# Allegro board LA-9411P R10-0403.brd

Outline 370.15 x 241.31 mm; copper layers: TOP, GND1, IN1, GND2, IN2, IN3, VCC, IN4, GND3, BOTTOM. Coordinates in mm from the lower left corner of the outline.

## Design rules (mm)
constraint set DEFAULT: min track width 0.102
net group AUDIO_L: nets INT_SPK_L+ INT_SPK_L-
net group AUDIO_R: nets INT_SPK_R+ INT_SPK_R-
net group CLK_BUF_BCLK: nets CLK_BUF_BCLK CLK_BUF_BCLK#
net group CLK_BUF_CKSSCD: nets CLK_BUF_CKSSCD CLK_BUF_CKSSCD#
net group CLK_BUF_DMI: nets CLK_BUF_DMI CLK_BUF_DMI#
net group CLK_BUF_DOT96: nets CLK_BUF_DOT96 CLK_BUF_DOT96#
net group CLK_CPU_DMI: nets CLK_CPU_DMI CLK_CPU_DMI#
net group CLK_CPU_DPLL: nets CLK_CPU_DPLL CLK_CPU_DPLL#
net group CLK_CPU_ITP: nets CLK_CPU_ITP CLK_CPU_ITP#
net group CLK_CPU_SSC_DPLL: nets CLK_CPU_SSC_DPLL CLK_CPU_SSC_DPLL#
net group CLK_PCIE_EMB: nets CLK_PCIE_EMB CLK_PCIE_EMB#
net group CLK_PCIE_EXP: nets CLK_PCIE_EXP CLK_PCIE_EXP#
net group CLK_PCIE_LAN: nets CLK_PCIE_LAN CLK_PCIE_LAN#
net group CLK_PCIE_MINI2: nets CLK_PCIE_MINI2 CLK_PCIE_MINI2#
net group CLK_PCIE_MINI3: nets CLK_PCIE_MINI3 CLK_PCIE_MINI3#
net group CLK_PCIE_MMI: nets CLK_PCIE_MMI CLK_PCIE_MMI#
net group CLK_PCIE_VG: nets CLK_PCIE_VGA CLK_PCIE_VGA#
net group CLK_XDP: nets CLK_XDP CLK_XDP#
net group CLKA0: nets CLKA0 CLKA0#
net group CLKA1: nets CLKA1 CLKA1#
net group CLKB0: nets CLKB0 CLKB0#
net group CLKB1: nets CLKB1 CLKB1#
net group CVT_LVDS_A0: nets CVT_LVDS_A0+ CVT_LVDS_A0-
net group CVT_LVDS_A1: nets CVT_LVDS_A1+ CVT_LVDS_A1-
net group CVT_LVDS_A2: nets CVT_LVDS_A2+ CVT_LVDS_A2-
net group CVT_LVDS_ACLK: nets CVT_LVDS_ACLK+ CVT_LVDS_ACLK-
net group CVT_LVDS_B0: nets CVT_LVDS_B0+ CVT_LVDS_B0-
net group CVT_LVDS_B1: nets CVT_LVDS_B1+ CVT_LVDS_B1-
net group CVT_LVDS_B2: nets CVT_LVDS_B2+ CVT_LVDS_B2-
net group CVT_LVDS_BCLK: nets CVT_LVDS_BCLK+ CVT_LVDS_BCLK-
net group DDR_A_3: nets DDR_A_DQS3 DDR_A_DQS#3
net group DDR_A_5: nets DDR_A_DQS5 DDR_A_DQS#5
net group DDR_A_6: nets DDR_A_DQS6 DDR_A_DQS#6
net group DDR_A_7: nets DDR_A_DQS7 DDR_A_DQS#7
net group DDR_B_3: nets DDR_B_DQS3 DDR_B_DQS#3
net group DIFFPAIR0: nets BAY_SMBCLK BAY_SMBDAT
net group DIFFPAIR1: nets BC_CLK_ECE1117 BC_DAT_ECE1117
net group DIFFPAIR2: nets BC_CLK_ECE5048 BC_DAT_ECE5048
net group DIFFPAIR3: nets CARD_SMBCLK CARD_SMBDAT
net group DIFFPAIR4: nets CHARGER_SMBCLK CHARGER_SMBDAT
net group DIFFPAIR5: nets DDR_XDP_SMBCLK_R1 DDR_XDP_SMBDAT_R1
net group DIFFPAIR6: nets DDR_XDP_WAN_SMBCLK DDR_XDP_WAN_SMBDAT
net group DIFFPAIR7: nets DDR_XDP_WAN_SMBCLK_R2 DDR_XDP_WAN_SMBDAT_R2
net group DIFFPAIR8: nets DOCK_SMB_CLK DOCK_SMB_DAT
net group DIFFPAIR9: nets GPU_SMBCLK GPU_SMBDAT
net group DIFFPAIR11: nets HDMI_SCL_SINK HDMI_SDA_SINK
net group DIFFPAIR13: nets LCD_SMBCLK LCD_SMBDAT
net group DIFFPAIR14: nets PBAT_SMBCLK PBAT_SMBDAT
net group DIFFPAIR16: nets USH_SMBCLK USH_SMBDAT
net group DIFFPAIR18: nets Z4304 Z4305
net group DIFFPAIR27: nets INT_SPKL_L+ INT_SPKL_L-
net group DIFFPAIR30: nets DPD_DOCK_AUX DPD_DOCK_AUX#
net group DIFFPAIR31: nets DPC_DOCK_AUX DPC_DOCK_AUX#
net group DIFFPAIR32: nets Z5304 Z5305
net group DMI_CRX_PTX_0: nets DMI_CRX_PTX_N0 DMI_CRX_PTX_P0
net group DMI_CRX_PTX_1: nets DMI_CRX_PTX_N1 DMI_CRX_PTX_P1
net group DMI_CRX_PTX_2: nets DMI_CRX_PTX_N2 DMI_CRX_PTX_P2
net group DMI_CRX_PTX_3: nets DMI_CRX_PTX_N3 DMI_CRX_PTX_P3
net group DMI_CTX_PRX_0: nets DMI_CTX_PRX_N0 DMI_CTX_PRX_P0
net group DMI_CTX_PRX_1: nets DMI_CTX_PRX_N1 DMI_CTX_PRX_P1
net group DMI_CTX_PRX_2: nets DMI_CTX_PRX_N2 DMI_CTX_PRX_P2
net group DMI_CTX_PRX_3: nets DMI_CTX_PRX_N3 DMI_CTX_PRX_P3
net group DOCK_LOM_TRD0: nets DOCK_LOM_TRD0+ DOCK_LOM_TRD0-
net group DOCK_LOM_TRD1: nets DOCK_LOM_TRD1+ DOCK_LOM_TRD1-
net group DOCK_LOM_TRD2: nets DOCK_LOM_TRD2+ DOCK_LOM_TRD2-
net group DOCK_LOM_TRD3: nets DOCK_LOM_TRD3+ DOCK_LOM_TRD3-
net group DPC_CPU_LANE_0: nets DPC_CPU_LANE_N0 DPC_CPU_LANE_P0
net group DPC_CPU_LANE_0_C: nets DPC_CPU_LANE_N0_C DPC_CPU_LANE_P0_C
net group DPC_CPU_LANE_1: nets DPC_CPU_LANE_N1 DPC_CPU_LANE_P1
net group DPC_CPU_LANE_1_C: nets DPC_CPU_LANE_N1_C DPC_CPU_LANE_P1_C
net group DPC_CPU_LANE_2: nets DPC_CPU_LANE_N2 DPC_CPU_LANE_P2
net group DPC_CPU_LANE_2_C: nets DPC_CPU_LANE_N2_C DPC_CPU_LANE_P2_C
net group DPC_CPU_LANE_3: nets DPC_CPU_LANE_N3 DPC_CPU_LANE_P3
net group DPC_CPU_LANE_3_C: nets DPC_CPU_LANE_N3_C DPC_CPU_LANE_P3_C
net group DPC_DOCK_LANE_0: nets DPC_DOCK_LANE_N0 DPC_DOCK_LANE_P0
net group DPC_DOCK_LANE_1: nets DPC_DOCK_LANE_N1 DPC_DOCK_LANE_P1
net group DPC_DOCK_LANE_2: nets DPC_DOCK_LANE_N2 DPC_DOCK_LANE_P2
net group DPC_DOCK_LANE_3: nets DPC_DOCK_LANE_N3 DPC_DOCK_LANE_P3
net group DPC_PCH_DOCK_AUX: nets DPC_PCH_DOCK_AUX DPC_PCH_DOCK_AUX#
net group DPD_CPU_LANE1: nets DPD_CPU_LANE_N1 DPD_CPU_LANE_P1
net group DPD_CPU_LANE2: nets DPD_CPU_LANE_N2 DPD_CPU_LANE_P2
net group DPD_CPU_LANE3: nets DPD_CPU_LANE_N3 DPD_CPU_LANE_P3
net group DPD_DOCK_LANE_0: nets DPD_DOCK_LANE_N0 DPD_DOCK_LANE_P0
net group DPD_DOCK_LANE_1: nets DPD_DOCK_LANE_N1 DPD_DOCK_LANE_P1
net group DPD_DOCK_LANE_2: nets DPD_DOCK_LANE_N2 DPD_DOCK_LANE_P2
net group DPD_DOCK_LANE_3: nets DPD_DOCK_LANE_N3 DPD_DOCK_LANE_P3
net group DPD_PCH_DOCK_AUX: nets DPD_PCH_DOCK_AUX DPD_PCH_DOCK_AUX#
net group EDP_CPU_AUX: nets EDP_CPU_AUX EDP_CPU_AUX#
net group EDP_CPU_AUX_C: nets EDP_CPU_AUX#_C EDP_CPU_AUX_C
net group EDP_CPU_LANE_0: nets EDP_CPU_LANE_N0 EDP_CPU_LANE_P0
net group EDP_CPU_LANE_0_C: nets EDP_CPU_LANE_N0_C EDP_CPU_LANE_P0_C
net group EDP_CPU_LANE_1: nets EDP_CPU_LANE_N1 EDP_CPU_LANE_P1
net group EDP_CPU_LANE_1_C: nets EDP_CPU_LANE_N1_C EDP_CPU_LANE_P1_C
net group FDI_CTX_PRX_0: nets FDI_CTX_PRX_N0 FDI_CTX_PRX_P0
net group FDI_CTX_PRX_1: nets FDI_CTX_PRX_N1 FDI_CTX_PRX_P1
net group LAN_SMB: nets LAN_SMBCLK LAN_SMBDATA
net group LAN_SMB_R: nets LAN_SMBCLK_R LAN_SMBDATA_R
net group LAN_TX0: nets LAN_TX0+ LAN_TX0-
net group LAN_TX0R: nets LAN_TX0+R LAN_TX0-R
net group LAN_TX1: nets LAN_TX1+ LAN_TX1-
net group LAN_TX1R: nets LAN_TX1+R LAN_TX1-R
net group LAN_TX2: nets LAN_TX2+ LAN_TX2-
net group LAN_TX2R: nets LAN_TX2+R LAN_TX2-R
net group LAN_TX3: nets LAN_TX3+ LAN_TX3-
net group LAN_TX3R: nets LAN_TX3+R LAN_TX3-R
net group LCD_EDID_: nets LCD_EDID_CLK LCD_EDID_DATA
net group M_CLK_DDR1: nets M_CLK_DDR1 M_CLK_DDR#1
net group M_CLK_DDR2: nets M_CLK_DDR2 M_CLK_DDR#2
net group M_CLK_DDR3: nets M_CLK_DDR3 M_CLK_DDR#3
net group MEM_SMB: nets MEM_SMBCLK MEM_SMBDATA
net group NB_LAN_TX0: nets NB_LAN_TX0+ NB_LAN_TX0-
net group NB_LAN_TX1: nets NB_LAN_TX1+ NB_LAN_TX1-
net group NB_LAN_TX2: nets NB_LAN_TX2+ NB_LAN_TX2-
net group NB_LAN_TX3: nets NB_LAN_TX3+ NB_LAN_TX3-
net group PCH_CL_1: nets PCH_CL_CLK1 PCH_CL_DATA1
net group PCH_DDPC_CTRL: nets PCH_DDPC_CTRLCLK PCH_DDPC_CTRLDATA
net group PCH_DDPD_CTRL: nets PCH_DDPD_CTRLCLK PCH_DDPD_CTRLDATA
net group PCIE_PRX_EXPTX_7: nets PCIE_PRX_EXPTX_N7 PCIE_PRX_EXPTX_P7
net group PCIE_PRX_GLANTX_2: nets PCIE_PRX_GLANTX_N2 PCIE_PRX_GLANTX_P2
net group PCIE_PRX_GLANTX_2_C: nets PCIE_PRX_GLANTX_N2_C PCIE_PRX_GLANTX_P2_C
net group PCIE_PRX_MMITX_8: nets PCIE_PRX_MMITX_N8 PCIE_PRX_MMITX_P8
net group PCIE_PRX_WLANTX_3: nets PCIE_PRX_WLANTX_N3 PCIE_PRX_WLANTX_P3
net group PCIE_PTX_EMBRX_4: nets PCIE_PTX_EMBRX_N4 PCIE_PTX_EMBRX_P4
net group PCIE_PTX_EMBRX_4_C: nets PCIE_PTX_EMBRX_N4_C PCIE_PTX_EMBRX_P4_C
net group PCIE_PTX_EXPRX_7: nets PCIE_PTX_EXPRX_N7 PCIE_PTX_EXPRX_P7
net group PCIE_PTX_EXPRX_7_C: nets PCIE_PTX_EXPRX_N7_C PCIE_PTX_EXPRX_P7_C
net group PCIE_PTX_GLANRX_2_C: nets PCIE_PTX_GLANRX_N2_C PCIE_PTX_GLANRX_P2_C
net group PCIE_PTX_MMIRX_8: nets PCIE_PTX_MMIRX_N8 PCIE_PTX_MMIRX_P8
net group PCIE_PTX_WLANRX_3_C: nets PCIE_PTX_WLANRX_N3_C PCIE_PTX_WLANRX_P3_C
net group PECI: nets PECI_EC PECI_EC_R
net group PEG_CRX_GTX_0: nets PEG_CRX_GTX_N0 PEG_CRX_GTX_P0
net group PEG_CRX_GTX_2: nets PEG_CRX_GTX_N2 PEG_CRX_GTX_P2
net group PEG_CRX_GTX_3: nets PEG_CRX_GTX_N3 PEG_CRX_GTX_P3
net group PEG_CRX_GTX_4: nets PEG_CRX_GTX_N4 PEG_CRX_GTX_P4
net group PEG_CRX_GTX_5: nets PEG_CRX_GTX_N5 PEG_CRX_GTX_P5
net group PEG_CRX_GTX_7: nets PEG_CRX_GTX_N7 PEG_CRX_GTX_P7
net group PEG_CRX_GTX_C_0: nets PEG_CRX_GTX_C_N0 PEG_CRX_GTX_C_P0
net group PEG_CRX_GTX_C_2: nets PEG_CRX_GTX_C_N2 PEG_CRX_GTX_C_P2
net group PEG_CRX_GTX_C_3: nets PEG_CRX_GTX_C_N3 PEG_CRX_GTX_C_P3
net group PEG_CRX_GTX_C_4: nets PEG_CRX_GTX_C_N4 PEG_CRX_GTX_C_P4
net group PEG_CRX_GTX_C_5: nets PEG_CRX_GTX_C_N5 PEG_CRX_GTX_C_P5
net group PEG_CTX_GRX_0: nets PEG_CTX_GRX_N0 PEG_CTX_GRX_P0
net group PEG_CTX_GRX_1: nets PEG_CTX_GRX_N1 PEG_CTX_GRX_P1
net group PEG_CTX_GRX_2: nets PEG_CTX_GRX_N2 PEG_CTX_GRX_P2
net group PEG_CTX_GRX_3: nets PEG_CTX_GRX_N3 PEG_CTX_GRX_P3
net group PEG_CTX_GRX_4: nets PEG_CTX_GRX_N4 PEG_CTX_GRX_P4
net group PEG_CTX_GRX_5: nets PEG_CTX_GRX_N5 PEG_CTX_GRX_P5
net group PEG_CTX_GRX_6: nets PEG_CTX_GRX_N6 PEG_CTX_GRX_P6
net group PEG_CTX_GRX_7: nets PEG_CTX_GRX_N7 PEG_CTX_GRX_P7
net group PEG_CTX_GRX_C_0: nets PEG_CTX_GRX_C_N0 PEG_CTX_GRX_C_P0
net group PEG_CTX_GRX_C_1: nets PEG_CTX_GRX_C_N1 PEG_CTX_GRX_C_P1
net group PEG_CTX_GRX_C_2: nets PEG_CTX_GRX_C_N2 PEG_CTX_GRX_C_P2
net group PEG_CTX_GRX_C_6: nets PEG_CTX_GRX_C_N6 PEG_CTX_GRX_C_P6
net group PEG_CTX_GRX_C_7: nets PEG_CTX_GRX_C_N7 PEG_CTX_GRX_C_P7
net group PSATA_PRX_DTX_0_C: nets PSATA_PRX_DTX_N0_C PSATA_PRX_DTX_P0_C
net group PSATA_PTX_DRX_0_C: nets PSATA_PTX_DRX_N0_C PSATA_PTX_DRX_P0_C
net group REM_DIODE1_: nets REM_DIODE1_N REM_DIODE1_P
net group REM_DIODE2_: nets REM_DIODE2_N REM_DIODE2_P
net group REM_DIODE4_: nets REM_DIODE4_N REM_DIODE4_P
net group SATA_ODD_PRX_DTX_1: nets SATA_ODD_PRX_DTX_N1 SATA_ODD_PRX_DTX_P1
net group SATA_ODD_PRX_DTX_1_C: nets SATA_ODD_PRX_DTX_N1_C SATA_ODD_PRX_DTX_P1_C
net group SATA_ODD_PTX_DRX_1: nets SATA_ODD_PTX_DRX_N1 SATA_ODD_PTX_DRX_P1
net group SATA_PRX_DKTX_2: nets SATA_PRX_DKTX_N2 SATA_PRX_DKTX_P2
net group SATA_PRX_DKTX_2_C: nets SATA_PRX_DKTX_N2_C SATA_PRX_DKTX_P2_C
net group SATA_PRX_DTX_0: nets SATA_PRX_DTX_N0 SATA_PRX_DTX_P0
net group SATA_PTX_DKRX_2: nets SATA_PTX_DKRX_N2 SATA_PTX_DKRX_P2
net group SATA_PTX_DKRX_2_C: nets SATA_PTX_DKRX_N2_C SATA_PTX_DKRX_P2_C
net group SATA_PTX_DRX_0: nets SATA_PTX_DRX_N0 SATA_PTX_DRX_P0
net group SML1_SMB: nets SML1_SMBCLK SML1_SMBDATA
net group SRCCLK: nets CLK_PCIE_MINI1 CLK_PCIE_MINI1#
net group SW_LAN_TX0: nets SW_LAN_TX0+ SW_LAN_TX0-
net group SW_LAN_TX1: nets SW_LAN_TX1+ SW_LAN_TX1-
net group SW_LAN_TX2: nets SW_LAN_TX2+ SW_LAN_TX2-
net group SW_LAN_TX3: nets SW_LAN_TX3+ SW_LAN_TX3-
net group TMDSE_CON_0: nets TMDSE_CON_N0 TMDSE_CON_P0
net group TMDSE_CON_1: nets TMDSE_CON_N1 TMDSE_CON_P1
net group TMDSE_CON_2: nets TMDSE_CON_N2 TMDSE_CON_P2
net group TMDSE_CON_CLK: nets TMDSE_CON_CLK TMDSE_CON_CLK#
net group TMDSE_CPU_0_C: nets TMDSE_CPU_N0_C TMDSE_CPU_P0_C
net group TMDSE_CPU_1_C: nets TMDSE_CPU_N1_C TMDSE_CPU_P1_C
net group TMDSE_CPU_2_C: nets TMDSE_CPU_N2_C TMDSE_CPU_P2_C
net group TMDSE_CPU_CLK_C: nets TMDSE_CPU_CLK#_C TMDSE_CPU_CLK_C
net group TMDSE_RP_0: nets TMDSE_RP_N0 TMDSE_RP_P0
net group TMDSE_RP_1: nets TMDSE_RP_N1 TMDSE_RP_P1
net group TMDSE_RP_2: nets TMDSE_RP_N2 TMDSE_RP_P2
net group TMDSE_RP_CLK: nets TMDSE_RP_CLK TMDSE_RP_CLK#
net group TP_: nets TP_CLK TP_DATA
net group USB3R1: nets USB3RN1 USB3RP1
net group USB3R2_C: nets USB3RN2_C USB3RP2_C
net group USB3R2_D: nets USB3RN2_D- USB3RP2_D+
net group USB3R2_R: nets USB3RN2_R USB3RP2_R
net group USB3R2_RP: nets USB3RN2_RP USB3RP2_RP
net group USB3R3: nets USB3RN3 USB3RP3
net group USB3R5: nets USB3RN5 USB3RP5
net group USB3R5_D: nets USB3RN5_D- USB3RP5_D+
net group USB3R6: nets USB3RN6 USB3RP6
net group USB3R6_R: nets USB3RN6_R USB3RP6_R
net group USB3R6_RP: nets USB3RN6_RP USB3RP6_RP
net group USB3RN1_D: nets USB3RN1_D- USB3RP1_D+
net group USB3RN6_D: nets USB3RN6_D- USB3RP6_D+
net group USB3RP1_CO: nets USB3RN1_CO USB3RP1_CO
net group USB3RP2_CO: nets USB3RN2_CO USB3RP2_CO
net group USB3RP6_CO: nets USB3RN6_CO USB3RP6_CO
net group USB3T1: nets USB3TN1 USB3TP1
net group USB3T2: nets USB3TN2 USB3TP2
net group USB3T2_C: nets USB3TN2_C USB3TP2_C
net group USB3T2_D: nets USB3TN2_D- USB3TP2_D+
net group USB3T2_RP: nets USB3TN2_RP USB3TP2_RP
net group USB3T5: nets USB3TN5 USB3TP5
net group USB3T5_D: nets USB3TN5_D- USB3TP5_D+
net group USB3T6_C: nets USB3TN6_C USB3TP6_C
net group USB3T6_RP: nets USB3TN6_RP USB3TP6_RP
net group USB3T_1: nets USB3T_N1 USB3T_P1
net group USB3T_2: nets USB3T_N2 USB3T_P2
net group USB3TN1_D: nets USB3TN1_D- USB3TP1_D+
net group USB3TN6_D: nets USB3TN6_D- USB3TP6_D+
net group USB3TP1_CO: nets USB3TN1_CO USB3TP1_CO
net group USB3TP2_CO: nets USB3TN2_CO USB3TP2_CO
net group USB3TP6_CO: nets USB3TN6_CO USB3TP6_CO
net group USB30_20/15_20: nets USB3RN6_C USB3RP6_C
net group USBP0: nets USBP0+ USBP0-
net group USBP0_D: nets USBP0_D+ USBP0_D-
net group USBP0_R_D: nets USBP0_R_D+ USBP0_R_D-
net group USBP3: nets USBP3+ USBP3-
net group USBP4: nets USBP4+ USBP4-
net group USBP5: nets USBP5+ USBP5-
net group USBP6_R_D: nets USBP6_R_D+ USBP6_R_D-
net group USBP7: nets USBP7+ USBP7-
net group USBP9: nets USBP9+ USBP9-
net group USBP9_D: nets USBP9_D+ USBP9_D-
net group USBP10: nets USBP10+ USBP10-
net group USBP12: nets USBP12+ USBP12-
net group USBP12_D: nets USBP12_D+ USBP12_D-
net group VGA_THERMD: nets VGA_THERMDN VGA_THERMDP
net group VGAA-DBI: nets ADBIA0 ADBIA1
net group VGAB-DBI: nets ADBIB0 ADBIB1
net group VSENSE: nets VCCSENSE VSSSENSE
net group VSSENSE_R: nets VCCSENSE_R VSSSENSE_R
net group WCKA0: nets WCKA0_0 WCKA0B_0
net group WCKA0_1: nets WCKA0_1 WCKA0B_1
net group WCKA1_0: nets WCKA1_0 WCKA1B_0
net group WCKA1_1: nets WCKA1_1 WCKA1B_1
net group WCKB0_0: nets WCKB0_0 WCKB0B_0
net group WCKB0_1: nets WCKB0_1 WCKB0B_1
net group WCKB1_1: nets WCKB1_1 WCKB1B_1
net group WCKB1B_0: nets WCKB1_0 WCKB1B_0
net group 15: nets CLK_80H CLK_PCH_14M CLK_PCI_LOOPBACK CLK_SIO_14M JETWAY_14M JETWAY_CLK14M PCI_LOOPBACKOUT PCLK_80H PEG_COMP SATA_COMP SIO_14M USBRBIAS
net group 20: nets +RTC_CELL CFG_RCOMP CLK_PCI_5048 CLK_PCI_DOCK CLK_PCI_MEC DMI_IREF DMI_RCOMP PCH_PCIE_RCOMP PCI_5048 PCI_DOCK PCI_MEC
net group 25: nets EDP_COMP FDI_RCOMP SM_RCOMP0 SM_RCOMP1 SM_RCOMP2
net group AUDIO_CODEC: nets AUD_HP_OUT_L AUD_HP_OUT_L1 AUD_HP_OUT_L2 AUD_HP_OUT_R AUD_HP_OUT_R1 AUD_HP_OUT_R2 RING2_L
net group CARD-CLK: nets SD_D0_RCLK_P_MMC_D0 SD_D0_RCLKR_P SD_D1_RCLK_N SD_D1_RCLKR_N SD_UHS2_D0N SD_UHS2_D0N_R SD_UHS2_D0P SD_UHS2_D0P_R SD_UHS2_D1N SD_UHS2_D1N_R SD_UHS2_D1P SD_UHS2_D1P_R
net group CARD-READER: nets SD_CD# SD_CLK SD_CLK_R SD_CMD SD_D2 SD_D2_R SD_D3 SD_D3_R SD_WPI
net group CLK: nets BITCLK_TERM CLK_ENABLE#_VGA CLK_KBD CLK_MSE CLK_PCI_TPM CLKRUN# CLKTESTA CLKTESTB D_CLKRUN# DAI_12MHZ# DAI_BCLK# DMIC_CLK DMIC_CLK_L EC_32KHZ_ECE5048 EMBCLK_REQ# EXPCLK_REQ# GENLK_CLK GFX_CLK_REQ# GFX_CLK_REQ#_R I2S_BCLK I2S_MCLK ICLK_IREF JTAG_CLK LANCLK_REQ# LANCLK_REQ#_R MINI2CLK_REQ# MINI3CLK_REQ# MMICLK_REQ# N35569138 PCH_CLK_BIASREF PCI_TPM_TCM PEG_B_CLKRQ# PS2_CLK_TS SCLK SUSCLK XTALI XTALO
net group CPU: nets CPU_PLTRST# CPU_PLTRST#_R DDR3_DRAMRST#_CPU DDR3_DRAMRST#_R H_CPUPWRGD H_CPUPWRGD_XDP H_PM_SYNC H_PROCHOT# H_PROCHOT#_R H_THERMTRIP# H_THERMTRIP#_R PCH_JTAG_TCK PCH_JTAG_TMS PCH_PLTRST# PCH_PLTRST#_BUF PCH_PLTRST#_EC PLTRST_EMB# PLTRST_LAN# PLTRST_MMI# PLTRST_USH# PM_DRAM_PWRGD PM_DRAM_PWRGD_CPU PM_DRAM_PWRGD_R PROCHOT#_EC RUNPWROK_AND THERMATRIP2# THERMATRIP3# VCCPWRGOOD_0_R XDP_OBS0_R XDP_OBS1_R XDP_OBS2_R XDP_OBS3_R XDP_OBS4_R XDP_OBS5_R XDP_OBS6_R XDP_OBS7_R XDP_PRDY# XDP_PREQ# XDP_RST#_R XDP_TCLK XDP_TMS
net group CRT_10_20: nets CLK_DDC2_CRT CLK_DDC2_DOCK DAT_DDC2_CRT DAT_DDC2_DOCK HSYNC HSYNC_BUF HSYNC_DOCK PCH_CRT_DDC_CLK PCH_CRT_DDC_DAT PCH_CRT_HSYNC PCH_CRT_VSYNC VSYNC VSYNC_BUF VSYNC_DOCK
net group CRT_20: nets BLUE_CRT BLUE_DOCK GREEN_CRT GREEN_DOCK PCH_CRT_BLU PCH_CRT_GRN PCH_CRT_RED RED_CRT RED_DOCK
net group CTL-LINK: nets PCH_CL_RST1#
net group DDRADD_13_16_25: nets DDR_A_BS0 DDR_A_BS1 DDR_A_BS2 DDR_A_CAS# DDR_A_MA0 DDR_A_MA1 DDR_A_MA2 DDR_A_MA3 DDR_A_MA4 DDR_A_MA5 DDR_A_MA6 DDR_A_MA7 DDR_A_MA8 DDR_A_MA9 DDR_A_MA10 DDR_A_MA11 DDR_A_MA12 DDR_A_MA13 DDR_A_MA14 DDR_A_MA15 DDR_A_RAS# DDR_A_WE# DDR_B_BS0 DDR_B_BS1 DDR_B_BS2 DDR_B_CAS# DDR_B_MA0 DDR_B_MA1 DDR_B_MA2 DDR_B_MA3 DDR_B_MA4 DDR_B_MA5 DDR_B_MA6 DDR_B_MA7 DDR_B_MA8 DDR_B_MA9 DDR_B_MA10 DDR_B_MA11 DDR_B_MA12 DDR_B_MA13 DDR_B_MA14 DDR_B_MA15 DDR_B_RAS# DDR_B_WE# DDR_CKE0_DIMMA DDR_CKE1_DIMMA DDR_CKE2_DIMMB DDR_CKE3_DIMMB DDR_CS0_DIMMA# DDR_CS1_DIMMA# DDR_CS2_DIMMB# DDR_CS3_DIMMB# M_ODT0 M_ODT1 M_ODT2 M_ODT3
net group DDRD0_8/10_16_25: nets DDR_A_D0 DDR_A_D1 DDR_A_D2 DDR_A_D3 DDR_A_D4 DDR_A_D5 DDR_A_D6 DDR_A_D7 DDR_A_D16 DDR_A_D17 DDR_A_D18 DDR_A_D19 DDR_A_D20 DDR_A_D21 DDR_A_D22 DDR_A_D23 DDR_A_D32 DDR_A_D33 DDR_A_D34 DDR_A_D35 DDR_A_D36 DDR_A_D37 DDR_A_D38 DDR_A_D39 DDR_A_D48 DDR_A_D49 DDR_A_D50 DDR_A_D51 DDR_A_D52 DDR_A_D53 DDR_A_D54 DDR_A_D55 DDR_B_D0 DDR_B_D1 DDR_B_D2 DDR_B_D3 DDR_B_D4 DDR_B_D5 DDR_B_D6 DDR_B_D7 DDR_B_D16 DDR_B_D17 DDR_B_D18 DDR_B_D19 DDR_B_D20 DDR_B_D21 DDR_B_D22 DDR_B_D23 DDR_B_D32 DDR_B_D33 DDR_B_D34 DDR_B_D35 DDR_B_D36 DDR_B_D37 DDR_B_D38 DDR_B_D39 DDR_B_D48 DDR_B_D49 DDR_B_D50 DDR_B_D51 DDR_B_D52 DDR_B_D53 DDR_B_D54 DDR_B_D55
net group DDRD1_8_16_25: nets DDR_A_D8 DDR_A_D9 DDR_A_D10 DDR_A_D11 DDR_A_D12 DDR_A_D13 DDR_A_D14 DDR_A_D15 DDR_A_D24 DDR_A_D25 DDR_A_D26 DDR_A_D27 DDR_A_D28 DDR_A_D29 DDR_A_D30 DDR_A_D31 DDR_A_D40 DDR_A_D41 DDR_A_D42 DDR_A_D43 DDR_A_D44 DDR_A_D45 DDR_A_D46 DDR_A_D47 DDR_A_D56 DDR_A_D57 DDR_A_D58 DDR_A_D59 DDR_A_D60 DDR_A_D61 DDR_A_D62 DDR_A_D63 DDR_B_D8 DDR_B_D9 DDR_B_D10 DDR_B_D11 DDR_B_D12 DDR_B_D13 DDR_B_D14 DDR_B_D15 DDR_B_D24 DDR_B_D25 DDR_B_D26 DDR_B_D27 DDR_B_D28 DDR_B_D29 DDR_B_D30 DDR_B_D31 DDR_B_D40 DDR_B_D41 DDR_B_D42 DDR_B_D43 DDR_B_D44 DDR_B_D45 DDR_B_D46 DDR_B_D47 DDR_B_D56 DDR_B_D57 DDR_B_D58 DDR_B_D59 DDR_B_D60 DDR_B_D61 DDR_B_D62 DDR_B_D63
net group DIFFPAIR28: nets INT_SPKR_R-
net group DP: nets DPC_PCH_DOCK_AUX#_C DPC_PCH_DOCK_AUX_C DPD_CPU_LANE_N0 DPD_CPU_LANE_N0_C DPD_CPU_LANE_N1_C DPD_CPU_LANE_N2_C DPD_CPU_LANE_N3_C DPD_CPU_LANE_P0 DPD_CPU_LANE_P0_C DPD_CPU_LANE_P1_C DPD_CPU_LANE_P2_C DPD_CPU_LANE_P3_C DPD_PCH_DOCK_AUX_C
net group FDI-CTL: nets FDI_CSYNC FDI_CSYNC_R FDI_INT FDI_INT_R
net group HDA: nets MDC_SDIN PCH_AZ_BITCLK PCH_AZ_CODEC_BITCLK PCH_AZ_CODEC_RST# PCH_AZ_CODEC_SDIN0 PCH_AZ_CODEC_SDOUT PCH_AZ_CODEC_SYNC PCH_AZ_MDC_BITCLK PCH_AZ_MDC_RST# PCH_AZ_MDC_SDIN1 PCH_AZ_MDC_SDOUT PCH_AZ_MDC_SYNC PCH_AZ_RST# PCH_AZ_SDOUT PCH_AZ_SYNC
net group PCIE: nets MSATA_PRX_WANTX_N4_RP MSATA_PRX_WANTX_N4_RP_C MSATA_PRX_WANTX_P4_RP MSATA_PRX_WANTX_P4_RP_C MSATA_PTX_WANRX_N4_RP MSATA_PTX_WANRX_N4_RP_C MSATA_PTX_WANRX_P4_RP MSATA_PTX_WANRX_P4_RP_C PCIE_PRX_MMITX_N8_C PCIE_PRX_WPANTX_N6 PCIE_PRX_WPANTX_P6 PCIE_PTX_MMIRX_N8_C PCIE_PTX_WPANRX_N6 PCIE_PTX_WPANRX_N6_C PCIE_PTX_WPANRX_P6 PCIE_PTX_WPANRX_P6_C PCIE_SATA_PRX_WANTX_N4 PCIE_SATA_PRX_WANTX_N4_C PCIE_SATA_PRX_WANTX_P4 PCIE_SATA_PRX_WANTX_P4_C PCIE_SATA_PTX_WANRX_N4 PCIE_SATA_PTX_WANRX_N4_C PCIE_SATA_PTX_WANRX_P4 PCIE_SATA_PTX_WANRX_P4_C
net group PCIE_PRX_MMITX_8_C: nets PCIE_PRX_MMITX_P8_C
net group PCIE_PTX_MMIRX_8_C: nets PCIE_PTX_MMIRX_P8_C
net group POWER-20: nets +3.3V_M +PCH_VCCCLK +VGA_PCIE_SPLL_VDDC
net group RTC: nets PCH_RTCRST# PCH_RTCX1 PCH_RTCX1_R PCH_RTCX2 SRTCRST#
net group SMBUS: nets CLK_TP_SIO DAT_TP_SIO MSCLK MSDATA PCH_DDPB_CTRLCLK PCH_DDPB_CTRLDATA
net group SPI: nets PCH_SPI_CLK PCH_SPI_CS0# PCH_SPI_CS1# PCH_SPI_DIN PCH_SPI_DO PCH_SPI_DO2 PCH_SPI_DO3 SPI_CLK32 SPI_CLK64 SPI_DIN32 SPI_DIN64 SPI_DO32 SPI_DO64 SPI_PCH_CLK SPI_PCH_CS0# SPI_PCH_CS0#_R SPI_PCH_CS1# SPI_PCH_CS1#_R SPI_PCH_DIN SPI_PCH_DO SPI_PCH_DO2 SPI_PCH_DO2_32 SPI_PCH_DO2_64 SPI_PCH_DO3 SPI_PCH_DO3_32 SPI_PCH_DO3_64
net group SVID: nets H_CPU_SVIDALRT# VIDALERT_N VIDSCLK VIDSOUT
net group USB20: nets USBP1_D+ USBP1_D- USBP2_D+ USBP2_D-
net group USB30: nets USB3RN1_C USB3RN1_R USB3RN1_RP USB3RN5_C USB3RN5_CO USB3RN5_R USB3RN5_RP USB3RP1_C USB3RP1_R USB3RP1_RP USB3RP5_C USB3RP5_CO USB3RP5_R USB3RP5_RP USB3T_N5 USB3T_N6 USB3T_P5 USB3T_P6 USB3TN1_C USB3TN1_RP USB3TN5_C USB3TN5_CO USB3TN5_RP USB3TP1_C USB3TP1_RP USB3TP5_C USB3TP5_CO USB3TP5_RP
net group VGAA-ADD: nets MAA0_0 MAA0_1 MAA0_2 MAA0_3 MAA0_4 MAA0_5 MAA0_6 MAA0_7 MAA0_8 MAA1_0 MAA1_1 MAA1_2 MAA1_3 MAA1_4 MAA1_5 MAA1_6 MAA1_7 MAA1_8
net group VGAA-CTL: nets CASA0# CASA1# CKEA0 CKEA1 CSA0#_0 CSA1#_0 RASA0# RASA1# WEA0# WEA1#
net group VGAA-D0: nets DDBIA0_0 DQA0_0 DQA0_1 DQA0_2 DQA0_3 DQA0_4 DQA0_5 DQA0_6 DQA0_7 EDCA0_0
net group VGAA-D1: nets DDBIA0_1 DQA0_8 DQA0_9 DQA0_10 DQA0_11 DQA0_12 DQA0_13 DQA0_14 DQA0_15 EDCA0_1
net group VGAA-D2: nets DDBIA0_2 DQA0_16 DQA0_17 DQA0_18 DQA0_19 DQA0_20 DQA0_21 DQA0_22 DQA0_23 EDCA0_2
net group VGAA-D3: nets DDBIA0_3 DQA0_24 DQA0_25 DQA0_26 DQA0_27 DQA0_28 DQA0_29 DQA0_30 DQA0_31 EDCA0_3
net group VGAA-D4: nets DDBIA1_0 DQA1_0 DQA1_1 DQA1_2 DQA1_3 DQA1_4 DQA1_5 DQA1_6 DQA1_7 EDCA1_0
net group VGAA-D5: nets DDBIA1_1 DQA1_8 DQA1_9 DQA1_10 DQA1_11 DQA1_12 DQA1_13 DQA1_14 DQA1_15 EDCA1_1
net group VGAA-D6: nets DDBIA1_2 DQA1_16 DQA1_17 DQA1_18 DQA1_19 DQA1_20 DQA1_21 DQA1_22 DQA1_23 EDCA1_2
net group VGAA-D7: nets DDBIA1_3 DQA1_24 DQA1_25 DQA1_26 DQA1_27 DQA1_28 DQA1_29 DQA1_30 DQA1_31 EDCA1_3
net group VGAB-ADD: nets MAB0_0 MAB0_1 MAB0_2 MAB0_3 MAB0_4 MAB0_5 MAB0_6 MAB0_7 MAB0_8 MAB1_0 MAB1_1 MAB1_2 MAB1_3 MAB1_4 MAB1_5 MAB1_6 MAB1_7 MAB1_8
net group VGAB-CTL: nets CASB0# CASB1# CKEB0 CKEB1 CSB0#_0 CSB1#_0 RASB0# RASB1# WEB0# WEB1#
net group VGAB-D0: nets DDBIB0_0 DQB0_0 DQB0_1 DQB0_2 DQB0_3 DQB0_4 DQB0_5 DQB0_6 DQB0_7 EDCB0_0
net group VGAB-D1: nets DDBIB0_1 DQB0_8 DQB0_9 DQB0_10 DQB0_11 DQB0_12 DQB0_13 DQB0_14 DQB0_15 EDCB0_1
net group VGAB-D2: nets DDBIB0_2 DQB0_16 DQB0_17 DQB0_18 DQB0_19 DQB0_20 DQB0_21 DQB0_22 DQB0_23 EDCB0_2
net group VGAB-D3: nets DDBIB0_3 DQB0_24 DQB0_25 DQB0_26 DQB0_27 DQB0_28 DQB0_29 DQB0_30 DQB0_31 EDCB0_3
net group VGAB-D4: nets DDBIB1_0 DQB1_0 DQB1_1 DQB1_2 DQB1_3 DQB1_4 DQB1_5 DQB1_6 DQB1_7 EDCB1_0
net group VGAB-D5: nets DDBIB1_1 DQB1_8 DQB1_9 DQB1_10 DQB1_11 DQB1_12 DQB1_13 DQB1_14 DQB1_15 EDCB1_1
net group VGAB-D6: nets DDBIB1_2 DQB1_16 DQB1_17 DQB1_18 DQB1_19 DQB1_20 DQB1_21 DQB1_22 DQB1_23 EDCB1_2
net group VGAB-D7: nets DDBIB1_3 DQB1_24 DQB1_25 DQB1_26 DQB1_27 DQB1_28 DQB1_29 DQB1_30 DQB1_31 EDCB1_3
nets with their own width: min track width 0.254; nets 3301_ACAV_IN_NB 3301_PWRSRC +1.2V_OZ_AUX_LDO +3.3V_OZ_IO_LDO +3.3V_RUN_DVDD +3.3V_SPI +VGA_COREP ACAV_IN_NB ACAVDK_SRC ACAVIN AUD_SENSE_A AUD_SENSE_B BQ24715_REGN CD3301_DCIN CD3301_SDC_IN CD_PBATT_OFF CHGVR_DCIN COMP CSS_GC CSSN_1 CSSP_1 DC_BLOCK_GC DC_IN_SS DEFAULT_OVRDE DEFAULT_OVRDE_C2 DGPU_PWR_EN DK_AC_OFF DK_AC_OFF_EN DK_CSS_GC DK_PWRBAR DOCK_AC_OFF_EC DOCK_DCIN_IS- DOCK_SMB_ALERT#_C2 DPRSLPVR_R EN_DK_PWRBAR EN_DOCK_PWR_BAR ERC1 FB FB2/VSEN FDI_IREF GNDA_GPU_CORE GPU_VDD_SENSE IMON ISEN1 ISEN1_VGA ISEN2 ISEN2_VGA ISEN3 ISUMN ISUMP MB_MBSS_GC MB_MBSS_GC_C2 N115634 N388738 N388758 N513876 N513898 N514008 N514014 N743839 N18894707 N18894708 N18894710 N18894855 N18894871 N18894895 N48716673 N48716693 N51922312 N51922324 N51922366 N51922457 N51922467 N51922473 N51922501 N51922603 N51922663 N51922909 N51924346 N78946737 N78957489 N78964443 N78999867 N79023703 N79033064 N79033066 N79033085 N79033110 N79099120 N79099356 N79099392 N79099442 N79100287 N79100289 N79108872 N79109047 N91583233 N91583241 N91583245 N117654516 NTC P1_SW P2_SW P3_SW PB_PBSS_GC PB_PBSS_GC_C2 PROCHOT_AD_POTC PROCHOT_AD_POTC_C2 PWM3 SL_BAT_PRES# SLICE_BAT_ON SLICE_BAT_ON_C2 SLICE_BAT_PRES# SLICE_BAT_PRES#_C2 SOFT_START_GC STSTART_DCBLOCK_GC V1N V1N_VGA V1P_VGA V2N V2N_VGA V2P_VGA V3N VCC_PGOOD VCP VSUM-_VGA
nets with their own width: min track width 0.381; nets +UIM_VPP AUD_HP_NB_SENSE N117653907
nets with their own width: min track width 0.508; nets +1.2V_LDO +1.05V_+1.5V_RUN +1.05V_M +1.05V_RUN +1.05V_RUN_CHG +1.5V_RUNP +1.8V_RUN_CARD +1.8V_RUN_GFX +1.35V_CPU_VDDQ +1.35V_MEM +1.35V_MEM_GFX +3.3V_ALW +3.3V_ALW2 +3.3V_ALW2_C2 +3.3V_ALW_PCH +3.3V_ALW_PCH_JTAG +3.3V_ALW_VTR +3.3V_CARDAUX +3.3V_LAN +3.3V_LAN_OUT +3.3V_RP1 +3.3V_RP2 +3.3V_RP4 +3.3V_RUN +3.3V_RUN_FFS +3.3V_RUN_GFX +3.3V_RUN_HDD_R +3.3V_SUS +3.3V_TP +3.3V_VTR +5V_ALW +CAP_LDO +CHGR_DC_IN +COINCELL +DC_IN_SS +DCIN +DDR_CHG +DIMM1_VREF_CA +DIMM1_VREF_DQ +DIMM2_VREF_CA +DIMM2_VREF_DQ +DOCK_PWR_BAR +DVDD_CORE +GPU_CORE +LOM_VCT +MBATT +MBATT_C +MBATT_C2 +MPBATT_IN_SS +NBDOCK_DC_IN_SS +PBATT +PBATT_C +PBATT_C2 +PBATT_IN_SS +PCH_DCPRTC +PCH_USB_DCPSUS1 +PCH_USB_DCPSUS2 +PCH_USB_DCPSUS3 +PCH_VCC +PCH_VCCCFUSE +PCH_VCCCLK3_3 +PCH_VCCDSW +PCH_VCCDSW3_3 +PCH_VCCDSW_R +PCH_VCCSST +PECI_VREF +PWR_SRC_AC +PWR_SRC_S +RSVD_VCC3P3_1 +RTC_CELL_VBAT +SA_DIMM_VREFDQ +SDC_IN +SIM_PWR +SM_VREF +TRM_CT1 +TRM_CT2 +TRM_CT3 +TRM_CT4 +TSVDD +VCC_CORE +VCCADAC +VCCIO2PCH +VCCIO2PCH_R +VCCIO_OUT +VCCST +VCHGR +VCHGR_C2 +VCOMP_OUT +VDD_MEM15_REFDA +VDD_MEM15_REFDB +VDD_MEM15_REFSA +VDD_MEM15_REFSB +VDDC_CT +VR_CAP +VREFOUT BAT1_LED# BAT1_LED#_Q BAT2_LED# BAT2_LED#_Q BATDRV# GND GND_CHASSIS GNDA GNDA_CHG INT_SPKR_R+ N115227 N18894698 N48716711 N74863185 N79100387 N79111305 N91583217 P33ALW RUN_ON_CPU1.5VS3# VCORE_VDDP VREFC1 VREFC2 VREFC3 VREFC4 VREFC5 VREFC6 VREFC7 VREFC8 VREFD1_1 VREFD1_2 VREFD2_1 VREFD2_2 VREFD3_1 VREFD3_2 VREFD4_1 VREFD4_2 VREFD5_1 VREFD5_2 VREFD6_1 VREFD6_2 VREFD7_1 VREFD7_2 VREFD8_1 VREFD8_2 Z2805 Z2806 Z2807 Z2808 Z4012
nets with their own width: min track width 0.635; nets BOOT1 BOOT1_1_VGA BOOT1_VGA BOOT2 BOOT2_2_VGA BOOT2_VGA BOOT3 BOOT_1.35V N18894554 N48711348
nets with their own width: min track width 0.762; nets +1.2V_LDO_OZ +3.3V_RUN_OZVCC N18894680 N49563382 N49574226 VLDOIN_1.35V
nets with their own width: min track width 1.016; nets +0.9V_LAN +0.675V_DDR_VTT +1.5V_CARD +1.5V_RUN +1.5V_RUN_HDMI +3.3V_PCIE_FLASH +3.3V_RUN_CARD +3.3V_RUN_EDP +3.3V_RUN_TPM +5V_RUN +AVCC33 +CAMERA_VDD +DVCC33 +VDDA_AVDD +VDDA_PVDD +VDISPLAY_VCC CHG_LGATE CHG_PHASE CHG_UGATE DH_1.35V EXT_MIC LG_3V LG_5V LG_+1.05VSP LGATE1 LGATE1_VGA LGATE2 LGATE2_VGA LGATE3 PHASE1 PHASE1_VGA PHASE2 PHASE2_VGA PHASE3 RING2 SLEEVE SW_+1.05VSP UG_3V UG_5V UG_+1.05VSP UGATE1 UGATE1_VGA UGATE2 UGATE2_VGA UGATE3
nets with their own width: min track width 1.524; nets +1.8V_RUN_GFX_VDDR4 +3.3V_CARD +3.3V_RUN_HDD +3.3V_WLAN +SW_LX +SWR_V12
nets with their own width: min track width 2.032; nets +5V_HDD +BL_PWR_SRC +LCDVDD +PWR_SRC +V_DDR_REF
nets with their own width: min track width 3.048; nets +3.3V_PCIE_WWAN
nets with their own width: min track width 4.064; nets +5V_MOD +5V_USB_CHG_PWR
nets with their own width: min track width 5.08; nets +VGA_PCIE

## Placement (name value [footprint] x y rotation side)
C1  -  [C_0402]  10.37 216.78 90 top
C2  -  [C_0402]  330.06 194.91 270 top
C3  -  [C_0402]  331.07 194.91 270 top
C7  -  [C_0805]  117.46 93.45 270 bottom
C8  -  [C_0402]  144.64 95.44 90 bottom
C9  -  [C_0402]  312.36 151.23 270 top
C16  -  [C_0402]  160.69 135.01 0 top
C18  -  [C_0402]  282.05 121.68 90 top
C25  -  [C_0402]  183.5 169.51 270 top
C26  -  [C_0402]  179.03 171.92 180 top
C27  -  [C_0402]  179.13 173.62 180 top
C28  -  [C_0402]  183.75 176.72 90 top
C29  -  [C_0402]  184.77 176.72 90 top
C30  -  [C_0402]  189.12 174.45 0 top
C31  -  [C_0402]  27.54 196.43 270 top
C32  -  [C_0402]  29.83 206.69 90 top
C40  -  [C_0402]  179.88 156.26 180 top
C41  -  [C_0402]  179.88 157.28 180 top
C43  -  [C_0402]  177.99 160.9 0 bottom
C44  -  [C_0402]  298.61 139.59 0 top
C45  -  [C_0402]  298.61 140.6 0 top
C46  -  [C_0402]  15.86 208.47 90 top
C47  -  [C_0805]  17.38 208.58 90 top
C49  -  [C_0402]  177.99 159.88 0 bottom
C51  -  [C_0402]  266.3 85.57 0 top
C52  -  [C_0402]  266.3 86.49 0 top
C53  -  [C_0402]  266.3 83.54 0 top
C100  -  [C_0402]  169.99 138.57 180 top
C101  -  [C_0402]  169.99 137.55 180 top
C103  -  [C_0402]  169.99 136.54 180 top
C104  -  [C_0402]  169.99 139.59 180 top
C105  -  [C_0402]  169.99 140.6 180 top
C106  -  [C_0603]  172.39 140.86 0 bottom
C107  -  [C_0402]  172.37 139.59 0 bottom
C108  -  [C_0402]  172.37 138.57 0 bottom
C109  -  [C_0603]  173.53 128.66 180 top
C110  -  [C_0402]  174.35 135.06 90 bottom
C111  -  [C_0402]  169.99 135.52 180 bottom
C112  -  [C_0402]  175.62 143.26 90 top
C113  -  [C_0603]  179.18 132.92 270 bottom
C114  -  [C_0402]  177.91 132.93 270 bottom
C115  -  [C_0603]  176.64 135.08 90 bottom
C116  -  [C_0402]  175.37 135.06 90 bottom
C117  -  [C_0402]  177.91 135.06 90 bottom
C118  -  [C_0402]  169.99 135.52 180 top
C195  -  [C_0603]  348.41 163 90 bottom
C196  -  [C_0603]  347.14 163.02 90 bottom
C246  -  [C_0603]  178.48 152.54 0 bottom
C247  -  [C_0603]  178.48 151.27 0 bottom
C283  -  [C_0402]  295.89 120.28 180 top
C284  -  [C_0402]  292.08 125.54 90 top
C285  -  [C_0402]  295.89 118.12 180 top
C286  -  [C_0402]  292.54 121.11 180 top
C287  -  [C_0402]  294.95 122.82 180 top
C288  -  [C_0402]  213.15 52.28 315 bottom
C289  -  [C_0402]  218.23 51.52 315 bottom
C290  -  [C_0402]  280.09 106.82 180 top
C296  -  [C_0603]  178.48 150 0 bottom
C297  -  [C_0402]  177.71 145.17 0 bottom
C298  -  [C_0402]  175.42 168.8 0 top
C299  -  [C_0402]  194.59 163.95 0 top
C300  -  [C_0805]  195.04 165.13 90 top
C301  -  [C_0402]  188.95 165.68 270 top
C340  -  [C_0402]  28.56 196.43 270 top
C342  -  [C_0402]  22.46 196.43 270 top
C344  -  [C_0402]  21.7 206.69 90 top
C346  -  [C_0402]  32.16 201.31 0 top
C347  -  [C_0402]  32.16 200.29 0 top
C348  -  [C_0402]  32.16 203.34 0 top
C349  -  [C_0402]  32.16 202.32 0 top
C350  -  [C_0402]  32.16 198.26 0 top
C351  -  [C_0402]  32.16 197.24 0 top
C352  -  [C_0402]  32.18 204.3 0 top
C353  -  [C_0402]  32.16 205.37 0 top
C354  -  [C_0402]  22.72 206.69 90 top
C355  -  [C_0402]  28.81 206.69 90 top
C356  -  [C_0402]  198.43 169.81 180 bottom
C357  -  [C_0402]  190.61 171.39 90 bottom
C360  -  [C_0402]  190.61 174.33 270 bottom
C365  -  [C_0402]  177.91 170.52 0 bottom
C366  -  [C_0402]  181.47 176.47 90 bottom
C367  -  [C_0402]  189.09 174.33 270 bottom
C368  -  [C_0402]  189.09 171.39 90 bottom
C369  -  [C_0402]  201.86 177.03 90 bottom
C383  -  [C_0402]  115.22 61.86 0 bottom
C384  -  [C_0402]  115.22 60.85 0 bottom
C385  -  [C_0402]  111.92 58.05 0 top
C386  -  [C_0402]  111.92 57.04 0 top
C387  -  [C_0603]  117.97 13.66 90 bottom
C388  -  [C_0402]  116.19 9.99 270 bottom
C393  -  [C_0402]  323.58 135.65 270 top
C394  -  [C_0402]  324.59 135.65 270 top
C395  -  [C_0402]  112.84 41.54 180 top
C396  -  [C_0402]  112.84 40.53 180 top
C397  -  [C_0402]  230.74 40.64 90 bottom
C398  -  [C_0402]  230.65 38.13 270 bottom
C399  -  [C_0402]  112.84 49.16 180 top
C400  -  [C_0402]  326.4 133.82 0 top
C401  -  [C_0402]  320.28 127.16 270 top
C402  -  [C_0402]  112.84 47.89 180 top
C403  -  [C_0402]  320.73 135.65 270 top
C404  -  [C_0402]  230.69 33.48 180 bottom
C405  -  [C_0402]  230.69 32.21 180 bottom
C406  -  [C_0402]  230.69 30.18 180 bottom
C407  -  [C_0402]  230.69 28.91 180 bottom
C408  -  [C_0402]  230.69 35.77 180 bottom
C409  -  [C_0402]  230.69 34.75 180 bottom
C410  -  [C_0402]  321.75 135.65 270 top
C412  -  [C_0402]  326.4 132.91 0 top
C414  -  [C_0402]  31.05 185.31 180 bottom
C415  -  [C_0402]  31.05 186.32 180 bottom
C416  -  [C_0402]  321.14 126.76 270 top
C417  -  [C_0402]  322.16 126.76 270 top
C420  -  [C_0402]  31.05 185.31 180 top
C421  -  [C_0402]  31.05 186.32 180 top
C422  -  [C_0402]  324.19 126.76 270 top
C423  -  [C_0805]  228.96 40.25 90 bottom
C424  -  [C_0402]  323.17 126.76 270 top
C445  -  [C_0402]  284.32 177.86 270 bottom
C446  -  [C_0603]  281.15 179.31 90 bottom
C447  -  [C_0603]  321.24 204.11 90 top
C448  -  [C_0402]  324.24 203.73 90 top
C449  -  [C_0603]  287.3 179.3 90 bottom
C450  -  [C_0402]  285.22 177.86 270 bottom
C451  -  [C_0603]  326.3 203.75 90 top
C452  -  [C_0402]  325.2 203.72 90 top
C454  -  [C_0603]  303.09 194.79 0 bottom
C455  -  [C_0402]  302.05 194.55 90 bottom
C456  -  [C_0402]  301.14 194.55 90 bottom
C458  -  [C_0402]  320.71 201.31 0 bottom
C459  -  [C_0402]  320.71 200.29 0 bottom
C460  -  [C_0402]  321.62 199.28 180 bottom
C461  -  [C_0402]  321.62 198.26 180 bottom
C462  -  [C_0603]  315.32 189.81 270 bottom
C463  -  [C_0402]  314.05 189.83 270 bottom
C464  -  [C_0603]  315.83 195.78 90 top
C465  -  [C_0402]  248.64 139.52 270 top
C466  -  [C_0402]  318.32 201.05 180 top
C467  -  [C_0402]  313.47 199.78 0 top
C468  -  [C_0402]  314.18 196.53 90 top
C469  -  [C_0402]  318.32 198.77 180 top
C470  -  [C_0402]  311.31 191.66 0 bottom
C471  -  [C_0402]  310.75 192.72 90 bottom
C472  -  [C_0402]  298.1 202.83 0 bottom
C473  -  [C_0402]  307.15 202.83 180 bottom
C474  -  [C_0402]  302.12 200.09 90 bottom
C475  -  [C_0603]  300.05 195.1 180 bottom
C476  -  [C_0402]  247.3 139.51 270 top
C477  -  [C_0402]  174.79 165.62 0 top
C478  -  [C_0402]  312.53 207.96 90 bottom
C479  -  [C_0603]  300.08 208.99 90 bottom
C480  -  [C_0603]  301.35 208.99 90 bottom
C481  -  [C_0603]  315.45 218.01 270 bottom
C482  -  [C_0402]  314.31 217.51 270 bottom
C483  -  [C_0603]  307.7 208.99 90 bottom
C484  -  [C_0603]  308.97 208.99 90 bottom
C485  -  [C_1808]  305.16 210.82 90 bottom
C486  -  [C_0402]  174.79 164.73 0 top
C487  -  [C_0402]  226.37 36.91 0 bottom
C488  -  [C_0402]  226.37 37.79 0 bottom
C550  -  [C_0402]  293.99 128.36 270 top
C551  -  [C_0402]  297.04 128.36 270 top
C552  -  [C_0402]  292.97 128.36 270 top
C553  -  [C_0402]  295.28 139.59 180 top
C559  -  [C_0603]  244.76 43.32 0 top
C560  -  [C_0603]  244.27 40.02 0 top
C561  -  [C_0603]  253.31 38.82 180 top
C562  -  [C_0402]  250.73 38.7 90 top
C564  -  [C_0603]  245.98 53.16 270 top
C566  -  [C_0603]  247.51 37.79 90 top
C567  -  [C_0402]  249.08 56.27 0 top
C568  -  [C_0402]  249.08 57.29 0 top
C569  -  [C_0402]  249.08 55.26 0 top
C570  -  [C_0402]  258.71 32.21 90 top
C571  -  [C_0402]  249.08 54.24 0 top
C572  -  [C_0603]  259.95 31.95 90 top
C573  -  [C_0402]  252.64 52.97 0 top
C574  -  [C_0402]  256.07 43.57 0 top
C575  -  [C_0402]  249.46 39.61 270 top
C576  -  [C_0402]  249.84 49.8 0 top
C577  -  [C_0603]  249.98 51.7 0 top
C578  -  [C_0603]  252.65 54.24 0 top
C579  -  [C_0603]  246.17 34.68 180 top
C580  -  [C_0402]  245.93 33.41 180 top
C581  -  [C_0402]  245.68 42.24 180 top
C595  -  [C_0402]  256.9 176.62 270 bottom
C596  -  [C_0402]  266.05 188.4 90 top
C598  -  [C_0402]  267.06 188.4 90 top
C603  -  [C_0402]  263.51 176.62 270 bottom
C604  -  [C_0402]  274.68 176.62 270 bottom
C605  -  [C_0402]  251.49 176.42 0 bottom
C606  -  [C_0402]  269.6 188.4 90 top
C607  -  [C_0402]  264.52 175.7 90 bottom
C608  -  [C_0603]  270.87 189.31 270 top
C610  -  [C_0402]  350.38 199.48 270 bottom
C611  -  [C_0402]  326.45 200.29 180 bottom
C612  -  [C_0402]  345.93 206.08 270 top
C613  -  [C_0805]  344.53 205.97 270 top
C614  -  [C_0402]  338.95 202.12 90 top
C615  -  [C_D2]  334.88 204.61 270 top
C616  -  [C_0402]  246.74 175.09 270 top
C617  -  [C_0402]  309.48 181.29 90 top
C618  -  [C_0402]  310.5 181.29 90 top
C621  -  [C_0402]  313.8 184.34 90 top
C622  -  [C_0402]  306.69 175.96 90 top
C623  -  [C_0402]  317.86 177.13 270 top
C624  -  [C_0402]  307.7 176.87 270 top
C625  -  [C_0402]  294.75 176.21 90 top
C626  -  [C_0603]  312.53 184.35 90 top
C628  -  [C_0402]  248.78 174.97 270 top
C629  -  [C_0402]  251.11 174.89 0 top
C630  -  [C_0402]  250.05 174.59 270 top
C631  -  [C_0402]  258.22 184.04 0 top
C633  -  [C_0402]  272.98 39.51 180 top
C634  -  [C_0402]  268.28 34.43 180 top
C635  -  [C_0402]  276.26 35.45 0 top
C636  -  [C_0402]  245.73 175.09 270 top
C637  -  [C_0402]  276.26 34.43 0 top
C638  -  [C_0603]  276.3 33.32 0 top
C639  -  [C_0603]  244.46 175.08 270 top
C640  -  [C_0402]  268.28 35.45 180 top
C641  -  [C_0603]  268.27 36.72 180 top
C642  -  [C_0402]  276.26 37.22 0 top
C643  -  [C_0603]  276.27 38.49 0 top
C645  -  [C_0402]  280.73 31.38 180 top
C646  -  [C_0402]  280.73 32.4 180 top
C647  -  [C_0402]  279.81 36.46 0 top
C648  -  [C_0402]  279.81 37.48 0 top
C649  -  [C_0402]  280.73 34.43 180 top
C651  -  [C_D2]  346.92 223.66 0 top
C654  -  [C_0402]  333.23 223.48 270 top
C667  -  [C_APXK6R3ARA221MF451]  20.4 189.15 90 bottom
C668  -  [C_0402]  17.39 187.64 270 bottom
C675  -  [C_0402]  352.84 220.74 0 top
C676  -  [C_0805]  352.07 219.34 0 top
C677  -  [C_0402]  249.84 136.54 0 bottom
C678  -  [C_0402]  262.95 140.6 180 bottom
C679  -  [C_0402]  169.78 174.84 270 bottom
C680  -  [C_0402]  169.27 187.9 90 top
C681  -  [C_0402]  170.8 174.84 270 bottom
C682  -  [C_0402]  170.29 187.9 90 top
C683  -  [C_0402]  171.81 174.84 270 bottom
C684  -  [C_0402]  171.31 187.9 90 top
C685  -  [C_0402]  173.85 174.84 270 bottom
C686  -  [C_0402]  173.34 187.9 90 top
C687  -  [C_0402]  174.86 174.84 270 bottom
C688  -  [C_0402]  174.35 187.9 90 top
C689  -  [C_0402]  175.88 174.84 270 bottom
C690  -  [C_0402]  168.77 174.84 270 bottom
C691  -  [C_0402]  168.26 187.9 90 top
C692  -  [C_0402]  172.83 174.84 270 bottom
C693  -  [C_0402]  172.32 187.9 90 top
C694  -  [C_0402]  175.37 187.9 90 top
C695  -  [C_0402]  177.91 177.91 270 bottom
C696  -  [C_0402]  176.39 190.59 270 top
C697  -  [C_0402]  182.86 184.59 90 top
C698  -  [C_0402]  183.88 184.59 90 top
C699  -  [C_0402]  184.89 185.51 270 top
C700  -  [C_0402]  185.91 185.51 270 top
C701  -  [C_0402]  197.72 189.32 270 top
C702  -  [C_0603]  169.59 180.48 180 top
C703  -  [C_0603]  202.55 181.69 270 top
C704  -  [C_0402]  200.52 177.05 90 bottom
C705  -  [C_0603]  272.14 60.65 90 top
C706  -  [C_0402]  264.5 60.8 90 top
C707  -  [C_0402]  267.68 44.6 270 top
C708  -  [C_0402]  270.75 60.9 90 top
C709  -  [C_0402]  277.39 50.66 180 top
C710  -  [C_0402]  260.3 50.81 180 top
C712  -  [C_0402]  261.09 60.81 90 top
C713  -  [C_0402]  266.55 60.81 90 top
C714  -  [C_0603]  257.67 52.91 270 top
C715  -  [C_0402]  319.08 216.04 180 bottom
C716  -  [C_0402]  265.67 41.57 270 top
C717  -  [C_0402]  250.76 138.32 180 bottom
C718  -  [C_0603]  250.74 139.59 180 bottom
C719  -  [C_0805]  33.38 192.58 90 bottom
C720  -  [C_0402]  277.62 120.15 180 top
C721  -  [C_0402]  296.21 103.85 270 top
C722  -  [C_0402]  295.33 105.3 180 top
C723  -  [C_0402]  31.86 192.47 90 bottom
C724  -  [C_0402]  286.65 103.77 270 top
C725  -  [C_0402]  179.89 152.54 180 top
C726  -  [C_0402]  169.99 156.86 180 top
C733  -  [C_0402]  297.11 107.96 180 top
C734  -  [C_0402]  295.32 108.86 270 top
C735  -  [C_0402]  289.34 99.58 0 top
C736  -  [C_0402]  287.47 106.26 270 top
C737  -  [C_0402]  289.61 121.54 90 top
C739  -  [C_0402]  287.83 121.54 90 top
C740  -  [C_0402]  282.24 106.26 270 top
C741  -  [C_0402]  293.53 104.34 0 top
C742  -  [C_0402]  297.12 114.44 0 top
C743  -  [C_0402]  292.67 104.34 180 top
C744  -  [C_0402]  300.29 115.33 180 top
C746  -  [C_0402]  190.36 40.07 90 top
C747  -  [C_0402]  285.16 123.89 90 top
C749  -  [C_0402]  264.52 98.74 90 top
C750  -  [C_0402]  264.52 97.12 270 top
C751  -  [C_0402]  268.08 98.74 90 top
C752  -  [C_0402]  268.08 97.37 270 top
C755  -  [C_0402]  258.94 95.95 90 top
C756  -  [C_0402]  318.37 135.83 90 top
C757  -  [C_0402]  288.36 106.26 270 top
C758  -  [C_0402]  318.23 134.72 0 top
C759  -  [C_0402]  286.05 121.54 90 top
C760  -  [C_0603]  249.7 139.47 270 top
C761  -  [C_0805]  226.46 35.45 0 bottom
C762  -  [C_0603]  175.56 167.65 0 top
C765  -  [C_0603]  173.58 162.99 180 top
C771  -  [C_0603]  246.25 139.46 270 top
C772  -  [C_0603]  221.09 23.44 270 bottom
C773  -  [C_0402]  227.95 24.07 90 bottom
C774  -  [C_0402]  294.92 110.88 0 top
C775  -  [C_0402]  288.72 121.54 90 top
C776  -  [C_0402]  294.92 115.84 0 top
C777  -  [C_0402]  280.03 120.38 90 top
C778  -  [C_0402]  320.1 210.2 180 bottom
C779  -  [C_0603]  297.07 115.65 0 top
C780  -  [C_0402]  284.02 106.26 270 top
C781  -  [C_0402]  280.06 113.3 180 top
C782  -  [C_0603]  278.67 120.61 90 top
C783  -  [C_0603]  190.29 108.6 180 top
C800  -  [C_0402]  246.79 40.27 0 top
C801  -  [C_0402]  245.98 50.63 270 top
C802  -  [C_0402]  255.84 32.73 270 top
C952  -  [C_0603]  337.61 169.43 0 bottom
C953  -  [C_0402]  337.73 172.86 0 bottom
C954  -  [C_0805]  334.97 175.65 180 top
C955  -  [C_0805]  348.38 168.92 0 top
C956  -  [C_0805]  346.46 176.54 90 bottom
C957  -  [C_0402]  347.33 169.38 270 top
C958  -  [C_0805]  338.44 177.34 90 bottom
C959  -  [C_0402]  343.73 177.51 90 bottom
C960  -  [C_0805]  340.22 177.34 90 bottom
C961  -  [C_0402]  339.07 174.84 270 bottom
C962  -  [C_0603]  344.91 177.49 90 top
C963  -  [C_0805]  342.5 165.43 270 top
C965  -  [C_0603]  348.7 173.89 180 top
C967  -  [C_0603]  336.91 176.73 90 bottom
C968  -  [C_0402]  345.09 176.54 90 bottom
C969  -  [C_0805]  347.15 172.39 0 top
C970  -  [C_0603]  351.18 168.67 0 top
C972  -  [C_0402]  340.98 159.7 90 top
C973  -  [C_0402]  343.01 174.84 270 bottom
C974  -  [C_0402]  341.99 174.84 270 bottom
C975  -  [C_0402]  340.09 174.84 270 bottom
C976  -  [C_0402]  340.98 174.84 270 bottom
C977  -  [C_0402]  330.56 171.54 270 top
C978  -  [C_0402]  332.55 173.62 180 top
C984  -  [C_0603]  335.38 173.19 180 bottom
C986  -  [C_0402]  340.98 164.53 90 bottom
C987  -  [C_0402]  339.96 164.53 90 bottom
C989  -  [C_0402]  331.58 174.94 90 top
C994  -  [C_0402]  337.73 170.57 0 bottom
C998  -  [C_0402]  54.97 197.19 270 top
C1001  -  [C_0402]  51.93 197.24 270 top
C1004  -  [C_0402]  329.29 167.73 270 top
C1105  -  [C_0402]  334.17 169.68 0 top
C1106  -  [C_0402]  334.17 168.54 0 top
C1107  -  [C_0402]  347.33 167.6 270 top
C1167  -  [C_0402]  295.51 212.05 270 bottom
C1176  -  [C_D2]  330.06 204.61 270 top
C1177  -  [C_0805]  320.57 196.74 0 bottom
C1178  -  [C_0805]  318.63 194.11 90 top
C1206  -  [C_0402]  189.15 160.11 90 top
C1207  -  [C_0402]  189.15 162.78 270 top
C1211  -  [C_0402]  355.29 169.23 270 bottom
C1212  -  [C_0402]  354.95 172.91 90 top
C1213  -  [C_0402]  350.9 180 270 bottom
C1214  -  [C_0603]  348.38 167.14 0 top
C1215  -  [C_0402]  351.82 181.97 90 bottom
C1216  -  [C_0402]  200.76 39.48 90 top
C1247  -  [C_0805]  342.5 159.82 90 top
C1501  -  [C_0402]  244.76 48.15 0 top
C1502  -  [C_0603]  247.25 53.16 270 top
C1503  -  [C_0402]  247.51 50.63 270 top
C1504  -  [C_0603]  244.71 50.88 270 top
C1505  -  [C_0402]  248.78 50.63 270 top
C1506  -  [C_0402]  257.36 42.68 180 top
C1507  -  [C_0603]  248.52 53.16 270 top
C1508  -  [C_0402]  254.01 49.31 0 top
C1509  -  [C_0402]  255.68 40.25 180 top
C1510  -  [C_0402]  252.84 39.87 180 top
C1511  -  [C_0402]  244.76 41.29 0 top
C1512  -  [C_0805]  324.81 184.54 180 top
C1513  -  [C_0402]  326.2 187.34 180 top
C1514  -  [C_0402]  326.2 189.12 180 top
C1515  -  [C_0402]  326.2 186.32 180 top
C1516  -  [C_0402]  328.02 184.85 90 bottom
C1517  -  [C_0402]  329.04 184.85 90 bottom
C1518  -  [C_0402]  330.06 184.85 90 bottom
C1519  -  [C_0402]  331.07 184.85 90 bottom
C1520  -  [C_0402]  330.06 194.91 270 bottom
C1521  -  [C_0402]  331.07 194.91 270 bottom
C1522  -  [C_0402]  332.09 193.99 90 bottom
C1523  -  [C_APXK6R3ARA221MF451]  353.2 210.31 270 top
C1524  -  [C_0402]  353.42 213.55 90 top
C1525  -  [C_0805]  349.19 220.36 180 top
C1526  -  [C_0402]  348.8 218.96 180 top
C1527  -  [C_0805]  345.02 216.51 270 bottom
C1528  -  [C_0402]  342.81 217.06 0 bottom
C1529  -  [C_0402]  343.64 215.61 270 bottom
C1530  -  [C_0402]  342.63 215.61 270 bottom
C1531  -  [C_0402]  343.72 219.09 180 bottom
C1532  -  [C_0402]  343.72 220.1 180 bottom
C1533  -  [C_0402]  343.72 221.12 180 bottom
C1534  -  [C_0402]  343.72 222.14 180 bottom
C1535  -  [C_0402]  333.28 220.1 0 bottom
C1536  -  [C_0402]  333.28 221.12 0 bottom
C1537  -  [C_0402]  334.2 222.14 180 bottom
C1538  -  [C_0402]  337.13 191.1 180 top
C1539  -  [C_0402]  353.3 191.22 270 top
C1540  -  [C_0805]  348.69 206.39 180 top
C1541  -  [C_0402]  348.8 204.86 180 top
C1542  -  [C_0402]  31.86 188.91 90 bottom
C1543  -  [C_0402]  40.95 184.04 180 bottom
C1544  -  [C_0402]  41.26 179.67 270 bottom
C1545  -  [C_0805]  42.78 180.06 270 bottom
C1546  -  [C_0402]  40.95 185.31 180 bottom
C1547  -  [C_0402]  40.95 183.02 180 bottom
C1548  -  [C_0402]  40.24 179.67 270 bottom
C1549  -  [C_0402]  39.23 179.67 270 bottom
C1550  -  [C_0402]  40.95 186.32 180 bottom
C1551  -  [C_0402]  342.64 195.87 270 bottom
C1552  -  [C_0805]  336.77 189.03 270 top
C1553  -  [C_0402]  343.66 195.87 270 bottom
C1554  -  [C_0402]  343.4 186.19 90 bottom
C1555  -  [C_0402]  340.36 186.19 90 bottom
C1556  -  [C_0402]  341.37 186.19 90 bottom
C1557  -  [C_0402]  345.91 191.66 0 top
C1558  -  [C_0402]  337.13 190.21 180 top
C1559  -  [C_0402]  345.91 192.67 0 top
C1560  -  [C_0402]  333.28 220.1 0 top
C1561  -  [C_0402]  333.28 221.12 0 top
C1562  -  [C_0402]  342.39 186.19 90 bottom
C1563  -  [C_0402]  342.64 195.87 270 top
C1564  -  [C_0402]  343.66 195.87 270 top
CC1  -  [C_0402]  216.96 105.98 270 bottom
CC2  -  [C_0402]  215.95 105.98 270 bottom
CC3  -  [C_0402]  217.6 109.44 270 bottom
CC4  -  [C_0402]  216.58 109.44 270 bottom
CC5  -  [C_0402]  213.66 105.98 270 bottom
CC6  -  [C_0402]  212.64 105.98 270 bottom
CC7  -  [C_0402]  214.68 109.44 270 bottom
CC8  -  [C_0402]  213.66 109.44 270 bottom
CC9  -  [C_0402]  210.36 105.98 270 bottom
CC10  -  [C_0402]  209.34 105.98 270 bottom
CC11  -  [C_0402]  211.37 109.44 270 bottom
CC12  -  [C_0402]  210.36 109.44 270 bottom
CC13  -  [C_0402]  207.06 105.98 270 bottom
CC14  -  [C_0402]  206.04 105.98 270 bottom
CC15  -  [C_0402]  208.07 109.44 270 bottom
CC16  -  [C_0402]  207.06 109.44 270 bottom
CC17  -  [C_0402]  122.33 115.46 0 bottom
CC18  -  [C_0402]  113.32 112.53 0 top
CC19  -  [C_0402]  136.48 64.83 270 top
CC21  -  [C_0402]  126.81 99.71 180 bottom
CC22  -  [C_0402]  144.38 91.88 90 bottom
CC23  -  [C_0402]  144.38 91.88 90 top
CC24  -  [C_0805]  147.68 91.74 90 bottom
CC25  -  [C_0805]  149.46 91.74 90 bottom
CC26  -  [C_0805]  151.24 91.74 90 bottom
CC27  -  [C_0805]  154.8 91.74 90 bottom
CC28  -  [C_0805]  153.02 91.74 90 bottom
CC29  -  [C_0805]  160.64 91.74 90 bottom
CC30  -  [C_0805]  158.61 91.74 90 bottom
CC31  -  [C_0805]  156.57 91.74 90 bottom
CC32  -  [C_0805]  147.68 91.74 90 top
CC33  -  [C_0805]  149.46 91.74 90 top
CC34  -  [C_D2]  156.57 71.16 270 top
CC35  -  [C_D2]  161.4 71.16 270 top
CC36  -  [C_0805]  145.91 91.74 90 bottom
CC37  -  [C_0805]  162.67 91.74 90 bottom
CC38  -  [C_0805]  164.7 91.74 90 bottom
CC39  -  [C_0805]  164.7 91.74 90 top
CC40  -  [C_0805]  162.67 91.74 90 top
CC41  -  [C_0805]  156.57 91.74 90 top
CC42  -  [C_0805]  160.64 91.74 90 top
CC43  -  [C_0805]  151.24 91.74 90 top
CC44  -  [C_0805]  154.8 91.74 90 top
CC45  -  [C_0805]  158.61 91.74 90 top
CC46  -  [C_0805]  145.91 91.74 90 top
CC47  -  [C_0805]  129.65 119.18 90 bottom
CC48  -  [C_0805]  131.43 119.18 90 bottom
CC135  -  [C_0603]  152.68 72.21 270 top
CC136  -  [C_0402]  145.4 72.48 270 top
CC137  -  [C_0603]  179.08 99.71 90 bottom
CD1  -  [C_0402]  123 38.26 270 top
CD2  -  [C_0402]  122.05 38.26 270 top
CD3  -  [C_0402]  151.19 30.37 180 top
CD4  -  [C_0402]  157.08 37.93 270 top
CD5  -  [C_0402]  155.3 37.93 270 top
CD6  -  [C_0402]  149.46 37.93 270 top
CD7  -  [C_0603]  146.92 38.43 270 top
CD8  -  [C_0603]  152 38.43 270 top
CD9  -  [C_0603]  157.91 25.39 90 top
CD10  -  [C_0603]  156.89 30.37 0 top
CD11  -  [C_0603]  153.97 30.37 180 top
CD12  -  [C_0603]  147.49 30.37 0 top
CD13  -  [C_0603]  158.49 38.24 270 top
CD14  -  [C_APXK2R5ARA331MF451]  162.72 31.62 270 top
CD15  -  [C_0402]  162.97 23 0 top
CD16  -  [C_0402]  162.97 24.02 0 top
CD17  -  [C_0402]  185.67 42.11 90 top
CD18  -  [C_0402]  184.79 42.11 90 top
CD19  -  [C_0402]  184.93 40.54 180 top
CD20  -  [C_0402]  184.93 39.65 180 top
CD21  -  [C_0402]  187.56 42.1 90 top
CD22  -  [C_0402]  186.55 42.1 90 top
CD23  -  [C_0402]  124.58 25.02 90 top
CD24  -  [C_0402]  123.67 25.02 90 top
CD25  -  [C_0402]  149.67 26.56 180 top
CD26  -  [C_0402]  155.1 30.11 0 top
CD27  -  [C_0402]  155.76 19.19 180 top
CD28  -  [C_0402]  149.28 18.56 270 top
CD29  -  [C_0603]  160.38 25.09 90 top
CD30  -  [C_0603]  156.07 25.35 90 top
CD31  -  [C_0603]  153.08 26.56 0 top
CD32  -  [C_0603]  155.37 17.41 0 top
CD33  -  [C_0603]  152.83 17.41 0 top
CD34  -  [C_0603]  150.29 17.41 0 top
CD35  -  [C_0603]  147.7 18.56 270 top
CD36  -  [C_APXK2R5ARA331MF451]  144.26 38.96 0 top
CD37  -  [C_0402]  163.18 15.58 270 top
CD38  -  [C_0402]  163.13 17.02 0 top
CD39  -  [C_0402]  185.94 25.93 180 top
CD40  -  [C_0402]  185.94 26.82 180 top
CD41  -  [C_0402]  185.94 27.71 180 top
CD42  -  [C_0402]  185.94 32.85 180 top
CD43  -  [C_0402]  182.74 26.1 90 top
CD44  -  [C_0402]  183.75 26.1 90 top
CD45  -  [C_0402]  120.29 24.87 180 top
CD46  -  [C_0402]  128.86 25.79 180 top
CD47  -  [C_0402]  124.82 31.18 90 top
CD48  -  [C_0402]  168.16 16.76 90 top
CE1  -  [C_0402]  194.42 42.35 90 top
CE2  -  [C_0402]  203.86 39.48 90 top
CE3  -  [C_0402]  296.02 127.44 90 top
CE5  -  [C_0402]  15.1 204.3 270 bottom
CE6  -  [C_0805]  201.02 181.58 270 top
CE7  -  [C_0402]  15.1 205.17 90 bottom
CE8  -  [C_0402]  191.37 176.72 90 bottom
CE9  -  [C_0402]  188.32 176.72 90 bottom
CE10  -  [C_0402]  280.73 28.33 180 top
CE11  -  [C_0402]  280.73 35.45 180 top
CE12  -  [C_0402]  280.73 33.41 180 top
CE13  -  [C_0402]  16.11 201.76 270 bottom
CE14  -  [C_0402]  15.1 200.09 90 bottom
CE15  -  [C_0402]  15.1 199.22 270 bottom
CE16  -  [C_0402]  16.11 207.96 90 bottom
CE17  -  [C_0402]  16.11 206.84 270 bottom
CE18  -  [C_0402]  16.11 202.63 90 bottom
CE759  -  [C_0402]  256.98 45.61 180 top
CH2  -  [C_0402]  276.92 80.4 180 top
CH4  -  [C_0402]  207.6 55.63 315 top
CH5  -  [C_0402]  205.98 57.24 315 top
CH6  -  [C_0402]  211.85 56.45 135 top
CH7  -  [C_0402]  209.94 58.36 315 top
CH8  -  [C_0402]  221.66 63.07 315 bottom
CH9  -  [C_0402]  332.55 172.61 180 top
CH10  -  [C_0402]  191.13 62.62 315 bottom
CH11  -  [C_0402]  207.65 52.3 315 bottom
CH12  -  [C_0402]  188.36 67.46 135 top
CH13  -  [C_0402]  213.21 85.23 45 bottom
CH14  -  [C_0402]  214.54 89.11 315 bottom
CH15  -  [C_0402]  223.22 72.83 45 top
CH16  -  [C_0402]  221.9 75.5 315 top
CH17  -  [C_0402]  192.58 68.8 135 top
CH18  -  [C_0402]  220.18 78.74 315 top
CH19  -  [C_0402]  219.55 78.12 315 top
CH20  -  [C_0603]  220.93 79.47 315 top
CH21  -  [C_0603]  200.34 77.39 225 top
CH22  -  [C_0402]  204.48 75.76 135 top
CH23  -  [C_0402]  203.88 72.95 315 top
CH24  -  [C_0402]  204.81 74.09 315 top
